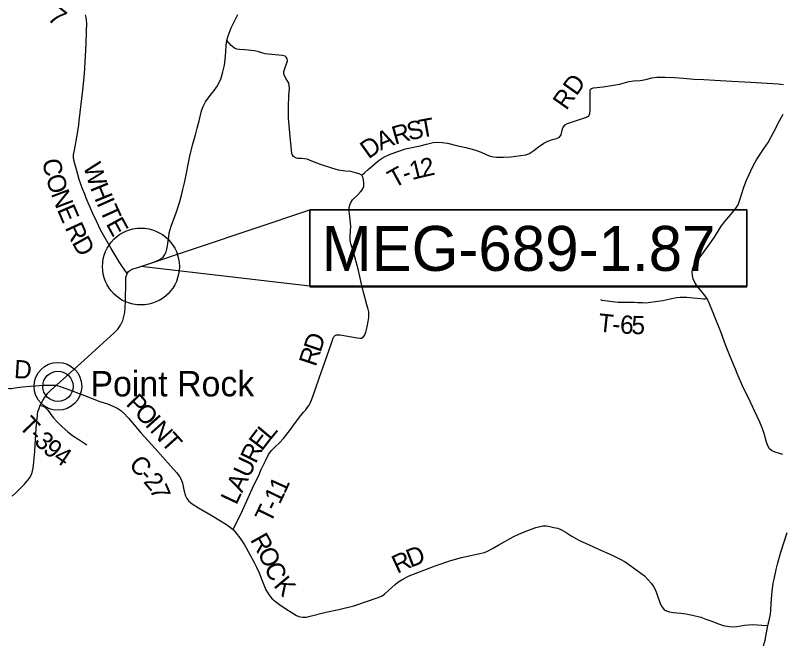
# Model space of a CAD drawing. Extents: x -15 to 405, y -40 to 87.
# Drawn here: x -11.395 to -9.003, y 24.452 to 26.393 of the extents above; entities that cross this region are included whole.
import ezdxf

# ---------------------------------------------------------------- set-up
doc = ezdxf.new("R2010")
doc.units = 0
for name, color, linetype in [('Default', 7, 'Continuous'), ('GM_P_County_Alignment', 7, 'Continuous'), ('GM_P_State_Location', 7, 'Continuous'), ('GM_X_Adjacent_County', 7, 'Continuous'), ('GM_X_County_ROW', 7, 'Continuous'), ('GM_X_Minor_Lake', 7, 'Continuous'), ('GM_X_Minor_River', 7, 'Continuous'), ('GM_X_State_Location', 7, 'Continuous'), ('GM_X_Township_ROW', 7, 'Continuous'), ('GM_X_Township_Subdivision_Text', 7, 'Continuous'), ('GM_X_Township_Text', 7, 'Continuous')]:
    doc.layers.add(name, color=color, linetype=linetype)

msp = doc.modelspace()

# ---------------------------------------------------------------- linework, layer by layer
at = {"layer": 'Default'}
msp.add_circle((-11.0033, 25.6111), 0.1198, dxfattribs=at)
at = {"layer": 'GM_P_State_Location'}
for points in [[(-11.0465, 25.589), (-11.0555, 25.6025), (-11.061, 25.6103), (-11.0711, 25.6259), (-11.0957, 25.6669), (-11.1288, 25.7232), (-11.1419, 25.7525), (-11.1538, 25.7788), (-11.1739, 25.8239), (-11.1786, 25.8369), (-11.1852, 25.8527), (-11.1956, 25.8824), (-11.2041, 25.9138), (-11.2095, 25.9313), (-11.2127, 25.9428), (-11.2133, 25.952), (-11.2131, 25.9592), (-11.2106, 25.9739), (-11.2013, 26.0259), (-11.1967, 26.0521), (-11.1954, 26.0648), (-11.184, 26.1605), (-11.1792, 26.2112), (-11.1741, 26.3035), (-11.1727, 26.3448), (-11.1723, 26.3673), (-11.1725, 26.379), (-11.1735, 26.3872), (-11.1764, 26.3948)], [(-10.7162, 24.7915), (-10.687, 24.8512), (-10.6509, 24.9305), (-10.6365, 24.9576), (-10.6284, 24.9789), (-10.6153, 25.0056), (-10.6057, 25.0258), (-10.5977, 25.0369), (-10.5864, 25.0487), (-10.5708, 25.0631), (-10.5588, 25.0759), (-10.5375, 25.1033), (-10.5213, 25.1256), (-10.5051, 25.1472), (-10.4964, 25.1574), (-10.4891, 25.1646), (-10.4829, 25.1736), (-10.4792, 25.179), (-10.4756, 25.1858), (-10.4717, 25.1949), (-10.4598, 25.2272), (-10.4465, 25.2664), (-10.436, 25.2951), (-10.4095, 25.3726), (-10.4064, 25.3822), (-10.4043, 25.3875), (-10.4021, 25.3925), (-10.3982, 25.3966), (-10.3941, 25.3982), (-10.3885, 25.3988), (-10.3824, 25.3984), (-10.3296, 25.389), (-10.321, 25.3875), (-10.3154, 25.3884), (-10.3101, 25.3914), (-10.3064, 25.3964), (-10.3025, 25.4066), (-10.2986, 25.4235), (-10.2947, 25.4403), (-10.2933, 25.4518), (-10.2928, 25.4619), (-10.293, 25.4699), (-10.2951, 25.4781), (-10.2988, 25.4916), (-10.3082, 25.5274), (-10.3171, 25.5617), (-10.3255, 25.5986), (-10.3368, 25.6413), (-10.3403, 25.6565), (-10.3487, 25.6818), (-10.3507, 25.6929), (-10.3509, 25.7056), (-10.3491, 25.7366), (-10.3524, 25.7668), (-10.3538, 25.7836), (-10.354, 25.7945), (-10.3526, 25.8017), (-10.3495, 25.8105), (-10.3438, 25.8189), (-10.3269, 25.8347), (-10.3189, 25.8434), (-10.3123, 25.851), (-10.3084, 25.8608), (-10.3089, 25.8725), (-10.3103, 25.8869), (-10.3152, 25.8953), (-10.3228, 25.8996), (-10.3341, 25.9029), (-10.3489, 25.9066), (-10.3659, 25.9085), (-10.3873, 25.9113), (-10.4084, 25.9173), (-10.4433, 25.9292), (-10.4702, 25.9395), (-10.4854, 25.9452), (-10.4939, 25.9469), (-10.5033, 25.9473), (-10.5142, 25.9477), (-10.5218, 25.9497), (-10.5281, 25.9536), (-10.5323, 25.9598), (-10.5344, 25.9711), (-10.5353, 25.9855), (-10.5376, 26.005), (-10.5438, 26.0733), (-10.5429, 26.108), (-10.5423, 26.1434), (-10.5403, 26.1653), (-10.5411, 26.175), (-10.5427, 26.182), (-10.5454, 26.1875), (-10.5511, 26.1961), (-10.5561, 26.2055), (-10.5576, 26.2125), (-10.5578, 26.2182), (-10.5571, 26.2219), (-10.5541, 26.2313), (-10.5499, 26.2421), (-10.5469, 26.2516), (-10.5474, 26.2576), (-10.5503, 26.2627), (-10.5542, 26.2665), (-10.5632, 26.2687), (-10.5739, 26.2695), (-10.6063, 26.2727), (-10.6156, 26.2739), (-10.6237, 26.2759), (-10.6353, 26.2797), (-10.6496, 26.2833), (-10.6792, 26.2857), (-10.6963, 26.2868), (-10.7046, 26.2882), (-10.7115, 26.291), (-10.7225, 26.2996), (-10.7356, 26.3146)], [(-10.3152, 25.8953), (-10.3064, 25.9029), (-10.2953, 25.913), (-10.2809, 25.9257), (-10.2612, 25.9419), (-10.2481, 25.9508), (-10.2269, 25.9606), (-10.1998, 25.9705), (-10.1785, 25.9772), (-10.1329, 25.9871), (-10.113, 25.9918), (-10.0923, 25.9971), (-10.0824, 25.9983), (-10.0643, 25.9975), (-10.0473, 25.9951), (-10.0198, 25.9883), (-9.9906, 25.982), (-9.964, 25.9744), (-9.9432, 25.9669), (-9.9273, 25.96), (-9.9152, 25.9551), (-9.9038, 25.9526), (-9.8948, 25.9518), (-9.8736, 25.9522), (-9.8501, 25.9532), (-9.8036, 25.9589), (-9.7942, 25.962), (-9.7781, 25.9728), (-9.7644, 25.9834), (-9.7472, 25.9953), (-9.7354, 26.0018), (-9.7205, 26.0069), (-9.7076, 26.0098), (-9.699, 26.0145), (-9.6929, 26.0216), (-9.6899, 26.0357), (-9.688, 26.0433), (-9.6854, 26.0475), (-9.6805, 26.0524), (-9.6733, 26.0563), (-9.6147, 26.0759), (-9.6106, 26.078), (-9.6068, 26.0808), (-9.6045, 26.0878), (-9.6027, 26.0975), (-9.6027, 26.1392), (-9.6035, 26.1598), (-9.6021, 26.1633), (-9.5986, 26.1653), (-9.5931, 26.168), (-9.5621, 26.1705), (-9.5369, 26.1745), (-9.512, 26.1792), (-9.4812, 26.1876), (-9.4677, 26.1898), (-9.4467, 26.1904), (-9.4291, 26.1941), (-9.4112, 26.199), (-9.3948, 26.2011), (-9.3699, 26.2013), (-9.3401, 26.1996), (-9.3124, 26.1982), (-9.2799, 26.1947), (-9.2491, 26.1935), (-9.2144, 26.1919), (-9.1619, 26.1888), (-9.1017, 26.1849), (-9.0167, 26.1797), (-9.0004, 26.1781)], [(-9.5709, 25.508), (-9.5663, 25.5065), (-9.5492, 25.504), (-9.534, 25.5024), (-9.5153, 25.5005), (-9.4979, 25.5005), (-9.4791, 25.5005), (-9.4659, 25.5002), (-9.4546, 25.4993), (-9.4397, 25.4986), (-9.4304, 25.4982), (-9.4218, 25.4989), (-9.3917, 25.503), (-9.376, 25.5052), (-9.3573, 25.5091), (-9.3442, 25.5121), (-9.333, 25.5145), (-9.3225, 25.5157), (-9.3113, 25.5159), (-9.3017, 25.5156), (-9.2819, 25.5138), (-9.2693, 25.5128), (-9.2586, 25.5114), (-9.25, 25.5103), (-9.2436, 25.5105), (-9.2388, 25.5112)], [(-11.4189, 25.2327), (-11.4179, 25.2324), (-11.4115, 25.231), (-11.4063, 25.2312), (-11.4014, 25.2322), (-11.3889, 25.2344), (-11.3726, 25.2359), (-11.349, 25.238), (-11.3323, 25.239), (-11.3097, 25.2412), (-11.2835, 25.2416), (-11.2665, 25.2412)], [(-11.3173, 25.1797), (-11.3123, 25.1776), (-11.3044, 25.1736), (-11.2997, 25.1699), (-11.295, 25.1651), (-11.2877, 25.1557), (-11.284, 25.1499), (-11.2761, 25.1401), (-11.2666, 25.1289), (-11.2485, 25.1115), (-11.2307, 25.0957), (-11.2165, 25.0849), (-11.1968, 25.0719), (-11.1718, 25.0557)]]:
    msp.add_lwpolyline(points, dxfattribs=at)
at = {"layer": 'GM_X_Adjacent_County'}
for points in [[(-11.0033, 25.6111), (-10.4772, 25.7875), (-10.4772, 25.5498)], [(-9.1147, 25.7875), (-10.4772, 25.7875), (-10.4772, 25.5475), (-9.1147, 25.5475)], [(-10.4772, 25.7875), (-9.1147, 25.7875), (-9.1147, 25.5498), (-10.4772, 25.5498)]]:
    msp.add_lwpolyline(points, close=True, dxfattribs=at)
at = {"layer": 'GM_X_County_ROW'}
msp.add_line((-11.2621, 25.2379), (-11.2621, 25.2379), dxfattribs=at)
at = {"layer": 'GM_X_State_Location'}
msp.add_lwpolyline([(-11.4042, 24.8962), (-11.392, 24.9075), (-11.3756, 24.9242), (-11.3665, 24.9329), (-11.3504, 24.9522), (-11.3458, 24.9607), (-11.3427, 24.97), (-11.3395, 24.9832), (-11.337, 25.0021), (-11.336, 25.0143), (-11.3344, 25.0346), (-11.3334, 25.0549), (-11.3299, 25.107), (-11.3261, 25.1494), (-11.3242, 25.1596), (-11.321, 25.1687), (-11.3173, 25.1797), (-11.3094, 25.1939), (-11.3042, 25.2018), (-11.2985, 25.2097), (-11.293, 25.2164), (-11.2837, 25.2257), (-11.2665, 25.2412), (-11.1688, 25.3294), (-11.1322, 25.3633), (-11.0865, 25.4049), (-11.0755, 25.4158), (-11.0665, 25.428), (-11.0594, 25.4431), (-11.0563, 25.455), (-11.0539, 25.468), (-11.0519, 25.5009), (-11.0505, 25.5652), (-11.0503, 25.577), (-11.0486, 25.5834), (-11.0465, 25.589), (-11.0432, 25.5945), (-11.0376, 25.599), (-11.0288, 25.6039), (-11.0134, 25.608), (-10.9845, 25.6171), (-10.9629, 25.6245), (-10.9463, 25.6316), (-10.9344, 25.6403), (-10.9286, 25.6484), (-10.925, 25.6569), (-10.9221, 25.6653), (-10.9205, 25.6756), (-10.9168, 25.7041), (-10.9151, 25.7164), (-10.909, 25.7371), (-10.8928, 25.7815), (-10.8821, 25.8137), (-10.8757, 25.8371), (-10.8722, 25.8514), (-10.8669, 25.8759), (-10.8512, 25.9553), (-10.8423, 25.9893), (-10.8335, 26.0216), (-10.8281, 26.0419), (-10.8222, 26.0646), (-10.814, 26.0962), (-10.8097, 26.11), (-10.8025, 26.124), (-10.7873, 26.1441), (-10.7748, 26.1597), (-10.7649, 26.1738), (-10.759, 26.1849), (-10.7547, 26.1945), (-10.7485, 26.2171), (-10.743, 26.238), (-10.7405, 26.2559), (-10.7386, 26.2801), (-10.7378, 26.3004), (-10.7356, 26.3146), (-10.7317, 26.3296), (-10.7216, 26.355), (-10.714, 26.3708), (-10.7009, 26.3959)], dxfattribs=at)
at = {"layer": 'GM_X_Township_Subdivision_Text'}
for radius in [0.0744, 0.0472]:
    msp.add_circle((-11.2621, 25.2379), radius, dxfattribs=at)
at = {"layer": 'GM_X_Township_Text'}
for points in [[(-9.0021, 25.0252), (-9.0128, 25.0289), (-9.0235, 25.0322), (-9.0314, 25.0349), (-9.0375, 25.0383), (-9.0438, 25.0437), (-9.0478, 25.0507), (-9.0529, 25.0645), (-9.0602, 25.091), (-9.0667, 25.1083), (-9.0739, 25.1267), (-9.0907, 25.1617), (-9.1029, 25.1882), (-9.1127, 25.208), (-9.1251, 25.2322), (-9.1444, 25.2776), (-9.15, 25.2911), (-9.1669, 25.3312), (-9.1809, 25.3672), (-9.1953, 25.4073), (-9.2091, 25.4414), (-9.2193, 25.4666), (-9.2308, 25.4953), (-9.2388, 25.5112), (-9.2565, 25.5353), (-9.2693, 25.5504), (-9.2765, 25.5616), (-9.2817, 25.5723), (-9.2845, 25.5831), (-9.285, 25.5938), (-9.2838, 25.6015), (-9.2807, 25.611), (-9.2749, 25.6218), (-9.2626, 25.6384), (-9.2336, 25.6776), (-9.2158, 25.7026), (-9.1946, 25.7369), (-9.1837, 25.7509), (-9.1641, 25.7733), (-9.1498, 25.7911), (-9.1421, 25.8028), (-9.1346, 25.8254), (-9.1244, 25.8579), (-9.1158, 25.8799), (-9.095, 25.9251), (-9.0842, 25.9438), (-9.0628, 25.9764), (-9.0483, 25.9979), (-9.0305, 26.0301), (-9.0119, 26.0669), (-9.0018, 26.0861)], [(-11.2665, 25.2412), (-11.2554, 25.2375), (-11.2347, 25.2305), (-11.1789, 25.2094), (-11.1311, 25.1911), (-11.1078, 25.183), (-11.0857, 25.1744), (-11.0754, 25.1689), (-11.0658, 25.1627), (-11.0569, 25.1544), (-11.0424, 25.1388), (-11.0025, 25.0924), (-10.9593, 25.0446), (-10.9113, 24.9902), (-10.8915, 24.9683), (-10.8834, 24.9568), (-10.8782, 24.9472), (-10.8742, 24.9367), (-10.8695, 24.916), (-10.8648, 24.8971), (-10.8601, 24.8887), (-10.8537, 24.8804), (-10.8431, 24.8715), (-10.8234, 24.8593), (-10.7844, 24.8365), (-10.7367, 24.8075), (-10.7162, 24.7915), (-10.706, 24.781), (-10.6949, 24.7657), (-10.6809, 24.7439), (-10.6636, 24.7145), (-10.65, 24.6896), (-10.643, 24.6746), (-10.6351, 24.6567), (-10.6267, 24.6347), (-10.6141, 24.6037), (-10.6069, 24.5922), (-10.6006, 24.5834), (-10.5938, 24.5764), (-10.5842, 24.568), (-10.5667, 24.5554), (-10.5434, 24.5395), (-10.5265, 24.5289), (-10.5189, 24.524), (-10.5111, 24.5213), (-10.4993, 24.5192), (-10.4875, 24.5194), (-10.4799, 24.5213)], [(-10.4799, 24.5213), (-10.4266, 24.5343), (-10.3869, 24.5425), (-10.3394, 24.5539), (-10.2635, 24.5799), (-10.2516, 24.5852), (-10.2444, 24.5903), (-10.2306, 24.6025), (-10.211, 24.6204), (-10.2025, 24.6277), (-10.1874, 24.6373), (-10.1668, 24.6478), (-10.1405, 24.6576), (-10.0866, 24.6784), (-10.0377, 24.6956), (-10.0039, 24.7047), (-9.9708, 24.7124), (-9.9518, 24.7159), (-9.932, 24.7208), (-9.921, 24.7259), (-9.9077, 24.733), (-9.8872, 24.744), (-9.8431, 24.7689), (-9.8254, 24.7776), (-9.8109, 24.7841), (-9.7976, 24.789), (-9.7721, 24.7981), (-9.7593, 24.8013), (-9.7507, 24.8032), (-9.7395, 24.8034), (-9.7292, 24.8014), (-9.7158, 24.7985), (-9.7042, 24.7958), (-9.6921, 24.7911), (-9.6783, 24.7831), (-9.6626, 24.7727), (-9.646, 24.7624), (-9.6339, 24.7568), (-9.6085, 24.7453), (-9.5768, 24.7307), (-9.534, 24.7119), (-9.5114, 24.701), (-9.4944, 24.6909), (-9.4796, 24.6811), (-9.456, 24.6646), (-9.4334, 24.6475), (-9.4222, 24.6352), (-9.4133, 24.6247), (-9.4059, 24.6146), (-9.3994, 24.6032), (-9.3942, 24.5883), (-9.3858, 24.5651), (-9.3807, 24.5532), (-9.3779, 24.549), (-9.3727, 24.5422), (-9.3653, 24.5383), (-9.3555, 24.5357), (-9.3447, 24.5339), (-9.3326, 24.5329), (-9.3197, 24.5317), (-9.3045, 24.5296), (-9.2845, 24.525), (-9.2581, 24.5184), (-9.2427, 24.5129), (-9.2264, 24.5072), (-9.2028, 24.4981), (-9.1881, 24.4929), (-9.1701, 24.4895), (-9.1601, 24.489), (-9.1456, 24.4902), (-9.1216, 24.4935), (-9.0966, 24.4958), (-9.0679, 24.4944), (-9.0494, 24.4925)], [(-9.0494, 24.4925), (-9.0473, 24.5002), (-9.0439, 24.5136), (-9.0412, 24.5285), (-9.0403, 24.5411), (-9.0385, 24.5614), (-9.0368, 24.5883), (-9.0357, 24.5992), (-9.0322, 24.6244), (-9.0298, 24.637), (-9.0228, 24.6676), (-9.0181, 24.6886), (-9.0086, 24.7218), (-8.9892, 24.7827)], [(-9.0853, 24.3736), (-9.0733, 24.4037), (-9.0651, 24.4226), (-9.0577, 24.4475), (-9.0494, 24.4925)]]:
    msp.add_lwpolyline(points, dxfattribs=at)

# ---------------------------------------------------------------- texts
at = {"layer": 'GM_P_County_Alignment'}
for s in ['s', 'r']:
    msp.add_text(s, height=0.000189, dxfattribs=at).set_placement((-10.9047, 25.7249))
msp.add_text('689', height=0.000189, rotation=0, dxfattribs=at).set_placement((-10.9716, 25.7111))
at = {"layer": 'GM_X_Adjacent_County'}
msp.add_text('MEG-689-1.87', height=0.14, dxfattribs=at).set_placement((-10.4402, 25.5975))
at = {"layer": 'GM_X_Minor_Lake'}
for s, rotation, p in [('P', 314.1466, (-11.0528, 25.1811)), ('O', 312.1074, (-11.0265, 25.154)), ('I', 311.9988, (-10.993, 25.1169)), ('N', 312.0054, (-10.9774, 25.0996)), ('T', 312.0031, (-10.9439, 25.0624)), ('C', 310.991, (-11.0436, 24.9927)), ('-', 310.9869, (-11.013, 24.9575)), ('2', 310.901, (-10.9977, 24.9399)), ('7', 293.6035, (-10.9772, 24.9172)), ('R', 299.2908, (-10.6639, 24.7603)), ('O', 296.7117, (-10.6414, 24.7202)), ('D', 21.1845, (-10.163, 24.6726)), ('R', 24.8839, (-10.2045, 24.6534)), ('C', 292.3127, (-10.6194, 24.6766)), ('K', 310.1332, (-10.5917, 24.617))]:
    msp.add_text(s, height=0.0568, rotation=rotation, dxfattribs=at).set_placement(p)
at = {"layer": 'GM_X_Minor_River'}
for s, height, rotation, p in [('7', 0.0568, 321.5011, (-11.2975, 26.3811)), ('RD', 0.05682, 54.8048, (-9.6773, 26.0953)), ('T', 0.0568, 10.4022, (-10.1308, 26.0115)), ('R', 0.0568, 15.9298, (-10.2116, 25.9903)), ('S', 0.0568, 13.1627, (-10.1674, 26.0029)), ('A', 0.0568, 22.5036, (-10.2562, 25.9717)), ('D', 0.0568, 35.5504, (-10.2939, 25.9443)), ('2', 0.0568, 13.1452, (-10.1247, 25.8886)), ('C', 0.0568, 280.4832, (-11.3109, 25.9422)), ('W', 0.0568, 287.5425, (-11.184, 25.9244)), ('1', 0.0568, 13.8141, (-10.1585, 25.8803)), ('T', 0.0568, 28.6737, (-10.2142, 25.8538)), ('-', 0.0568, 18.7213, (-10.1793, 25.8732)), ('O', 0.0568, 287.3918, (-11.3006, 25.8891)), ('H', 0.0568, 292.2312, (-11.1625, 25.857)), ('N', 0.0568, 290.6856, (-11.2845, 25.838)), ('I', 0.0568, 294.0153, (-11.1428, 25.8089)), ('T', 0.0568, 294.3803, (-11.1332, 25.7873)), ('E', 0.0568, 293.3705, (-11.2657, 25.7885)), ('E', 0.0568, 298.6442, (-11.1136, 25.7445)), ('R', 0.0568, 294.5064, (-11.2412, 25.7324)), ('D', 0.0568, 298.7457, (-11.2198, 25.6858)), ('T', 0.0568, 354.0408, (-9.5799, 25.4089)), ('6', 0.0568, 357.3237, (-9.5109, 25.4027)), ('5', 0.0568, 358.2298, (-9.4749, 25.401)), ('-', 0.0568, 356.1262, (-9.5354, 25.4043)), ('D', 0.0568, 71.3531, (-10.4439, 25.3412)), ('R', 0.0568, 71.5626, (-10.4586, 25.297)), ('D', 0.0568, 356.404, (-11.4, 25.264)), ('T', 0.0568, 314.1, (-11.3866, 25.1114)), ('L', 0.0568, 50.3793, (-10.6009, 25.0675)), ('-', 0.0568, 314.6019, (-11.3567, 25.0805)), ('3', 0.0568, 316.1835, (-11.3391, 25.0627)), ('E', 0.0568, 52.7144, (-10.6262, 25.0342)), ('9', 0.0568, 318.8182, (-11.3117, 25.0365)), ('R', 0.0568, 63.9813, (-10.6452, 24.9947)), ('4', 0.0568, 325.7973, (-11.2794, 25.0089)), ('U', 0.0568, 64.6781, (-10.6665, 24.9497)), ('A', 0.0568, 64.6816, (-10.6878, 24.9045)), ('1', 0.0568, 65.762, (-10.5548, 24.9008)), ('L', 0.0568, 64.6808, (-10.706, 24.8661)), ('1', 0.0568, 64.4239, (-10.5706, 24.868)), ('-', 0.0568, 64.0741, (-10.5809, 24.8466)), ('T', 0.0568, 63.9869, (-10.5996, 24.8084))]:
    msp.add_text(s, height=height, rotation=rotation, dxfattribs=at).set_placement(p)
at = {"layer": 'GM_X_Township_ROW'}
msp.add_text('Point Rock', height=0.07898, rotation=0, dxfattribs=at).set_placement((-11.1607, 25.2066))

doc.saveas('drawing.dxf')
